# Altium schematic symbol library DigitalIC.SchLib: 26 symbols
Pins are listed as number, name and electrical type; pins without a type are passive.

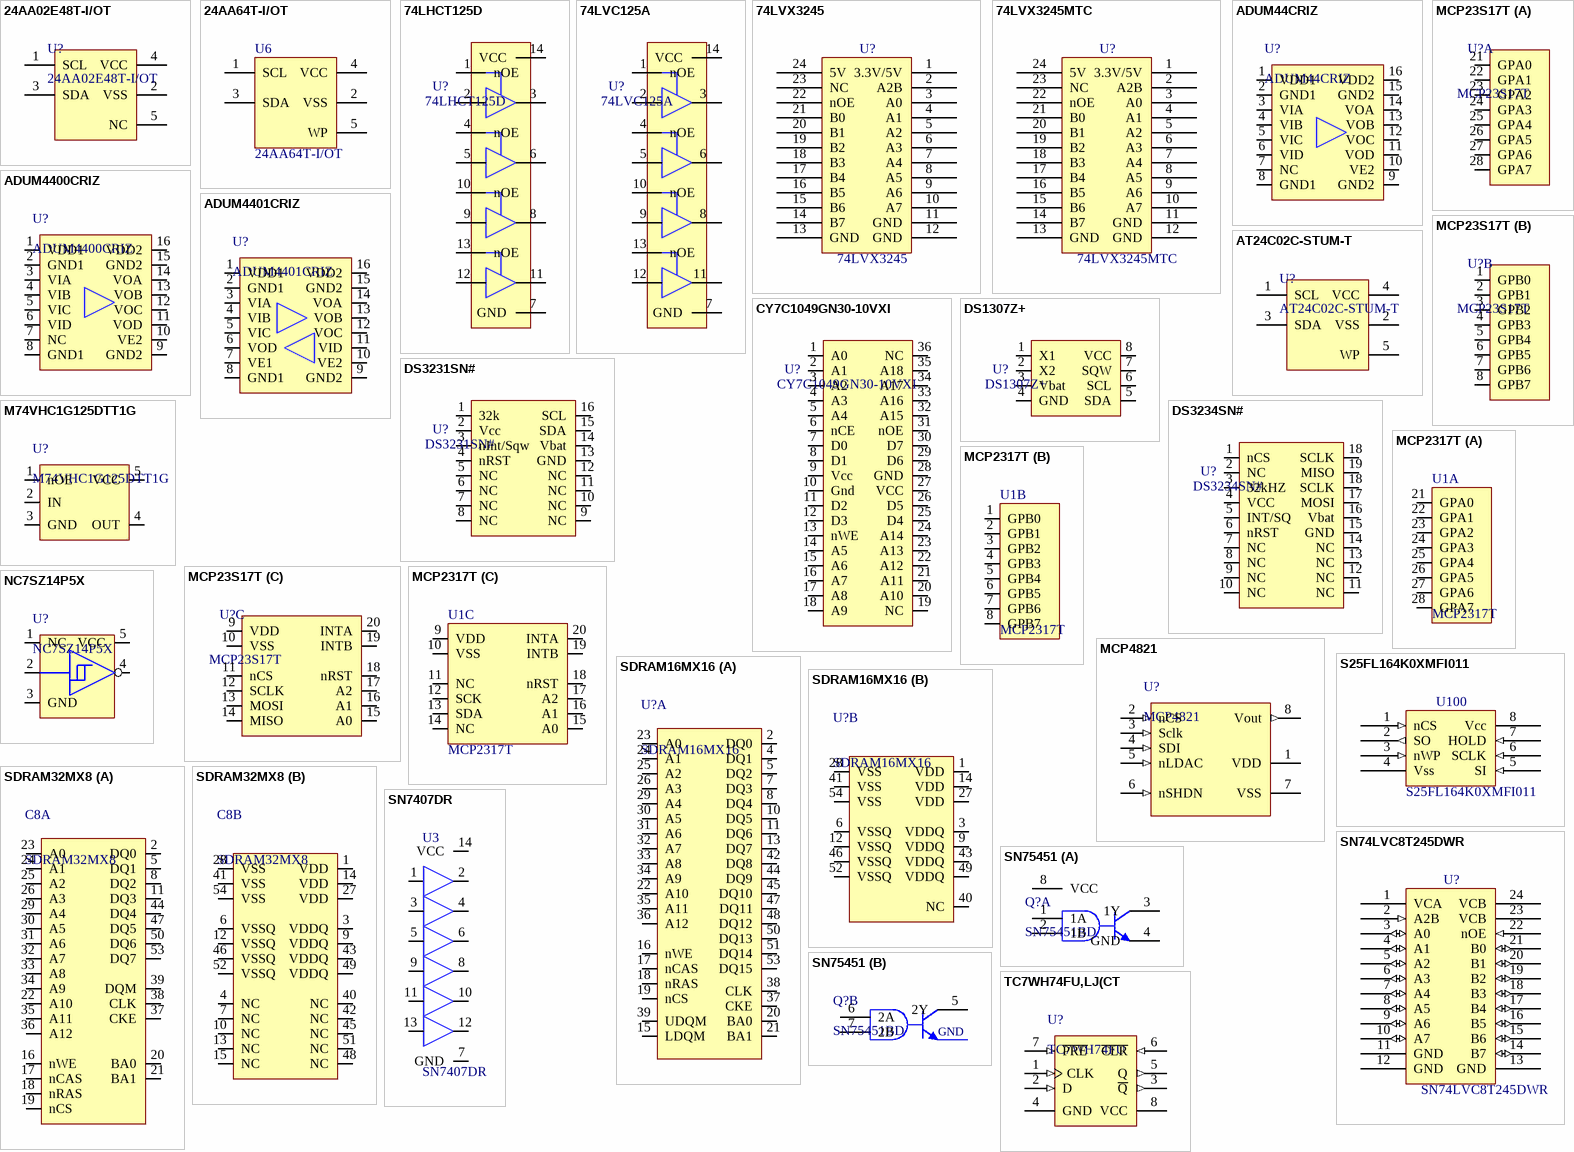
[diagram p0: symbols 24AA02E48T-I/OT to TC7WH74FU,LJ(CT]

## 24AA02E48T-I/OT
designator U?
IC EEPROM 2KBIT 400KHZ SOT23-5; MFG: Microchip; DK PN: 24AA02E48T-I/OTCT-ND
footprint SOT23-5
pins: 1 SCL, 2 VSS (power), 3 SDA, 4 VCC (power), 5 NC

## 24AA64T-I/OT
designator U6
IC EEPROM 64KBIT 400KHZ SOT23-5; MFG: Microchip; DK PN: 24AA64T-I/OTCT-ND
footprint SOT23-5
pins: 1 SCL, 2 VSS (power), 3 SDA, 4 VCC (power), 5 WP

## 74LHCT125D
designator U?
Buffer, Non-Inverting 4 Element 1 Bit per Element 3-State Output 14-SOIC; MFG: Nexpiria; MFG PN: 74HCT125D,653; DK PN: 1727-2834-2-ND
footprint SOP14
pins: 1 nOE, 2, 3, 4 nOE, 5, 6, 7 GND, 8, 9, 10 nOE, 11, 12, 13 nOE, 14 VCC

## 74LVC125A
designator U?
Buffer, Non-Inverting 4 Element 1 Bit per Element 3-State Output 14-SOIC; MFG: TI; MFG PN: SN74LVC125ADR; DK PN: 296-8453-2-ND
footprint SOP14
pins: 1 nOE, 2, 3, 4 nOE, 5, 6, 7 GND, 8, 9, 10 nOE, 11, 12, 13 nOE, 14 VCC

## 74LVX3245
designator U?
MFG: Fairchild; MFG PN: 74LVX3245WM; DK PN: 74LVX3245WM-ND
footprint SOL-24
pins: 1 3.3V/5V, 2 A2B, 3 A0, 4 A1, 5 A2, 6 A3, 7 A4, 8 A5, 9 A6, 10 A7, 11 GND, 12 GND, 13 GND, 14 B7, 15 B6, 16 B5, 17 B4, 18 B3, 19 B2, 20 B1, 21 B0, 22 nOE, 23 NC, 24 5V

## 74LVX3245MTC
designator U?
Voltage Level Translator Bidirectional 1 Circuit 8 Channel 24-TSSOP; MFG: Fairchild; DK PN: 74LVX3245MTC-ND
footprint TSOP24
pins: 1 3.3V/5V, 2 A2B, 3 A0, 4 A1, 5 A2, 6 A3, 7 A4, 8 A5, 9 A6, 10 A7, 11 GND, 12 GND, 13 GND, 14 B7, 15 B6, 16 B5, 17 B4, 18 B3, 19 B2, 20 B1, 21 B0, 22 nOE, 23 NC, 24 5V

## ADUM44CRIZ
designator U?
General Purpose Digital Isolator 5000Vrms 4 Channel 90Mbps 25kV/µs CMTI 16-SOIC (0.295", 7.50mm Width); MFG: Analog Devices; MFG PN: ADUM4400CRIZ; DK PN: ADUM4400CRIZ-ND
footprint AD_RI16
pins: 1 VDD1, 2 GND1, 3 VIA, 4 VIB, 5 VIC, 6 VID, 7 NC, 8 GND1, 9 GND2, 10 VE2, 11 VOD, 12 VOC, 13 VOB, 14 VOA, 15 GND2, 16 VDD2

## ADUM4400CRIZ
designator U?
General Purpose Digital Isolator 5000Vrms 4 Channel 90Mbps 25kV/µs CMTI 16-SOIC (0.295", 7.50mm Width); MFG: Analog Devices; DK PN: ADUM4400CRIZ-ND
footprint AD_RI16
pins: 1 VDD1, 2 GND1, 3 VIA, 4 VIB, 5 VIC, 6 VID, 7 NC, 8 GND1, 9 GND2, 10 VE2, 11 VOD, 12 VOC, 13 VOB, 14 VOA, 15 GND2, 16 VDD2

## ADUM4401CRIZ
designator U?
General Purpose Digital Isolator 5000Vrms 4 Channel 90Mbps 25kV/µs CMTI 16-SOIC (0.295", 7.50mm Width); MFG: Analog Devices; DK PN: ADUM4401CRIZ-ND
footprint AD_RI16
pins: 1 VDD1, 2 GND1, 3 VIA, 4 VIB, 5 VIC, 6 VOD, 7 VE1, 8 GND1, 9 GND2, 10 VE2, 11 VID, 12 VOC, 13 VOB, 14 VOA, 15 GND2, 16 VDD2

## AT24C02C-STUM-T
designator U?
IC EEPROM 2KBIT I2C 1MHZ SOT23-5; MFG: Microchip; DK PN: AT24C02C-STUM-TCT-ND - Cut Tape (CT)
footprint SOT23-5
pins: 1 SCL, 2 VSS (power), 3 SDA, 4 VCC (power), 5 WP

## CY7C1049GN30-10VXI
designator U?
SRAM - Asynchronous Memory IC 4Mb (512K x 8) Parallel 10ns 36-SOJ; MFG: Cypress; DK PN: 428-4393-ND
footprint SOJ36
pins: 1 A0, 2 A1, 3 A2, 4 A3, 5 A4, 6 nCE, 7 D0, 8 D1, 9 Vcc, 10 Gnd, 11 D2, 12 D3, 13 nWE, 14 A5, 15 A6, 16 A7, 17 A8, 18 A9, 19 NC, 20 A10, 21 A11, 22 A12, 23 A13, 24 A14, 25 D4, 26 D5, 27 VCC, 28 GND, 29 D6, 30 D7, 31 nOE, 32 A15, 33 A16, 34 A17, 35 A18, 36 NC

## DS1307Z+
designator U?
Real Time Clock (RTC) IC Clock/Calendar 56B I²C, 2-Wire Serial 8-SOIC (0.154", 3.90mm Width); MFG: Maxim; DK PN: DS1307Z+-ND
footprint SO-8
pins: 1 X1, 2 X2, 3 Vbat, 4 GND, 5 SDA, 6 SCL, 7 SQW, 8 VCC

## DS3231SN#
designator U?
Real Time Clock (RTC) IC Clock/Calendar I²C, 2-Wire Serial 16-SOIC (0.295", 7.50mm Width); MFG: Maxim; DK PN: DS3231SN#-ND
footprint SOL16
pins: 1 32k, 2 Vcc, 3 nInt/Sqw, 4 nRST, 5 NC, 6 NC, 7 NC, 8 NC, 9 NC, 10 NC, 11 NC, 12 NC, 13 GND, 14 Vbat, 15 SDA, 16 SCL

## DS3234SN#
designator U?
IC RTC CLK/CALENDAR SPI 20-SOIC; MFG: Maxim; DK PN: DS3234SN#-ND
footprint SOL20
pins: 1 nCS, 2 NC, 3 32kHZ, 4 VCC, 5 INT/SQ, 6 nRST, 7 NC, 8 NC, 9 NC, 10 NC, 11 NC, 12 NC, 13 NC, 14 NC, 15 GND, 16 Vbat, 17 MOSI, 18 SCLK, 18 SCLK, 19 MISO

## M74VHC1G125DTT1G
designator U?
Buffer, Non-Inverting 1 Element 1 Bit per Element Push-Pull Output 5-TSOP; DK PN: M74VHC1G125DTT1GOSCT-ND
footprint SOT23-5
pins: 1 nOE, 2 IN, 3 GND, 4 OUT, 5 VCC

## MCP23S17T
designator U?
I/O Expander 16 SPI 10MHz 28-SOIC; MFG PN: MCP23S17T-E/SO; DK PN: MCP23S17T-E/SOTR-ND; MFG: Microchip
footprint SOP28
part A pins: 21 GPA0, 22 GPA1, 23 GPA2, 24 GPA3, 25 GPA4, 26 GPA5, 27 GPA6, 28 GPA7
part B pins: 1 GPB0, 2 GPB1, 3 GPB2, 4 GPB3, 5 GPB4, 6 GPB5, 7 GPB6, 8 GPB7
part C pins: 9 VDD, 10 VSS, 11 nCS, 12 SCLK, 13 MOSI, 14 MISO, 15 A0, 16 A1, 17 A2, 18 nRST, 19 INTB, 20 INTA

## MCP2317T
designator U1
I/O Expander 16 SPI 10MHz 28-SOIC; MFG PN: MCP23017T-E/SO; MFG: Microchip
footprint SOP28
part A pins: 21 GPA0, 22 GPA1, 23 GPA2, 24 GPA3, 25 GPA4, 26 GPA5, 27 GPA6, 28 GPA7
part B pins: 1 GPB0, 2 GPB1, 3 GPB2, 4 GPB3, 5 GPB4, 6 GPB5, 7 GPB6, 8 GPB7
part C pins: 9 VDD, 10 VSS, 11 NC, 12 SCK, 13 SDA, 14 NC, 15 A0, 16 A1, 17 A2, 18 nRST, 19 INTB, 20 INTA

## MCP4821
designator U?
IC DAC 12BIT W/SPI 8SOIC; MFG PN: MCP4821-E/SN; DK PN: MCP4821-E/SN-ND; MFG: Microchip Technologies
footprint SO8
pins: 1 VDD (power), 2 nCS (in), 3 Sclk (in), 4 SDI (in), 5 nLDAC (in), 6 nSHDN (in), 7 VSS (power), 8 Vout (out)
1 alternate drawing of the same symbol

## NC7SZ14P5X
designator U?
Inverter IC 1 Channel Schmitt Trigger SC-70-5; MFG: On Semiconductor; DK PN: NC7SZ14P5XCT-ND
footprint SOT23-5
pins: 1 NC, 2, 3 GND, 4, 5 VCC

## S25FL164K0XMFI011
designator U100
IC FLASH 64MBIT 108MHZ 8SOIC; Text Field1: Cyoress; Text Field3: 1274-1097-ND
footprint SOC008
pins: 1 nCS (in), 2 SO (out), 3 nWP (in), 4 Vss (power), 5 SI (in), 6 SCLK (in), 7 HOLD (in), 8 Vcc (power)

## SDRAM16MX16
designator U?
SDRAM Memory IC 256Mb (16M x 16) Parallel 166MHz 5ns 54-TSOP II; MFG: Winbond; MFG PN: W9825G6KH-6; DK PN: W9825G6KH-6-ND
footprint SOP54
part A pins: 2 DQ0, 4 DQ1, 5 DQ2, 7 DQ3, 8 DQ4, 10 DQ5, 11 DQ6, 13 DQ7, 15 LDQM, 16 nWE, 17 nCAS, 18 nRAS, 19 nCS, 20 BA0, 21 BA1, 22 A10, 23 A0, 24 A1, 25 A2, 26 A3, 29 A4, 30 A5, 31 A6, 32 A7, 33 A8, 34 A9, 35 A11, 36 A12, 37 CKE, 38 CLK, 39 UDQM, 42 DQ8, 44 DQ9, 45 DQ10, 47 DQ11, 48 DQ12, 50 DQ13, 51 DQ14, 53 DQ15
part B pins: 1 VDD, 3 VDDQ, 6 VSSQ, 9 VDDQ, 12 VSSQ, 14 VDD, 27 VDD, 28 VSS, 40 NC, 41 VSS, 43 VDDQ, 46 VSSQ, 49 VDDQ, 52 VSSQ, 54 VSS

## SDRAM32MX8
designator C8
SDRAM Memory IC 256Mb (32M x 8) Parallel 166MHz 5.5ns 54-TSOP II; MFG: Alliance Memory; MFG PN: AS4C32M8SA-6TIN; DK PN: 1450-1440-ND
footprint SOP54
part A pins: 2 DQ0, 5 DQ1, 8 DQ2, 11 DQ3, 16 nWE, 17 nCAS, 18 nRAS, 19 nCS, 20 BA0, 21 BA1, 22 A10, 23 A0, 24 A1, 25 A2, 26 A3, 29 A4, 30 A5, 31 A6, 32 A7, 33 A8, 34 A9, 35 A11, 36 A12, 37 CKE, 38 CLK, 39 DQM, 44 DQ4, 47 DQ5, 50 DQ6, 53 DQ7
part B pins: 1 VDD, 3 VDDQ, 4 NC, 6 VSSQ, 7 NC, 9 VDDQ, 10 NC, 12 VSSQ, 13 NC, 14 VDD, 15 NC, 27 VDD, 28 VSS, 40 NC, 41 VSS, 42 NC, 43 VDDQ, 45 NC, 46 VSSQ, 48 NC, 49 VDDQ, 51 NC, 52 VSSQ, 54 VSS

## SN74LVC8T245DWR
designator U?
Voltage Level Translator Bidirectional 1 Circuit 8 Channel 24-SOIC; MFG: TI; DK PN: 296-23280-1-ND
footprint SOL-24
pins: 1 VCA (power), 2 A2B (in), 3 A0 (io), 4 A1 (io), 5 A2 (io), 6 A3 (io), 7 A4 (io), 8 A5 (io), 9 A6 (io), 10 A7 (io), 11 GND (power), 12 GND (power), 13 GND (power), 14 B7 (io), 15 B6 (io), 16 B5 (io), 17 B4 (io), 18 B3 (io), 19 B2 (io), 20 B1 (io), 21 B0 (io), 22 nOE (in), 23 VCB (power), 24 VCB (power)

## SN7407DR
designator U3
Buffer, Non-Inverting 6 Element 1 Bit per Element Open Collector Output 14-SOIC; DK PN: 296-1018-1-ND; MFG: TI
footprint SOP14
pins: 1, 2, 3, 4, 5, 6, 7 GND, 8, 9, 10, 11, 12, 13, 14 VCC

## SN75451
designator Q?, comment SN75451BD
IC PERIPHERAL DRVR DUAL HS 8SOIC; DK PN: 296-9912-5-ND; MFG: TI
footprint SO8
part A pins: 1 1A, 2 1B, 3 1Y, 4 GND (power), 8 VCC (power)
part B pins: 5 2Y, 6 2A, 7 2B

## TC7WH74FU,LJ(CT
designator U?, comment TC7WH74FU
IC D-TYPE POS TRG SNGL 8SSOP; MFG PN: TC7WH74FU,LJ(CT; DK PN: TC7WH74FULJ(CTTR-ND; MFG: Toshiba
footprint SSOP8
pins: 1 CLK (in), 2 D (in), 3 ~{Q} (out), 4 GND (power), 5 Q (out), 6 ~{CLR} (in), 7 ~{PRE} (in), 8 VCC (power)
